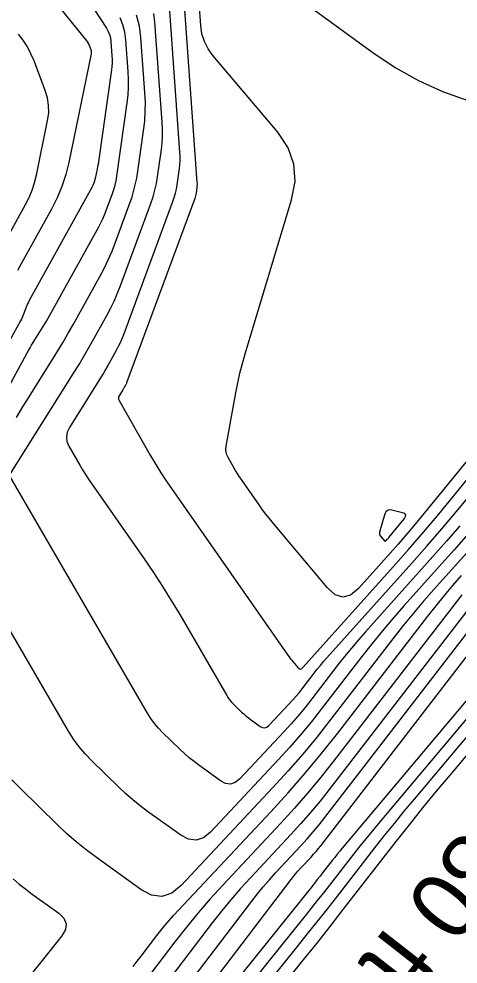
# Model space of a CAD drawing. Extents: x 7585033 to 7595090, y 547091 to 553471.
# Drawn here: x 7587336.2 to 7587377.6, y 548541.5 to 548630.8 of the extents above; entities that cross this region are included whole.
import ezdxf

# ---------------------------------------------------------------- set-up
doc = ezdxf.new("R2010")
doc.units = 0
for name, color, linetype in [('E_TERR_DSPLAY_GeneralTx', 7, 'Continuous'), ('E_TERR_DSPLAY_MajContour', 7, 'Continuous'), ('E_TERR_DSPLAY_MinContour', 7, 'Continuous')]:
    doc.layers.add(name, color=color, linetype=linetype)

msp = doc.modelspace()

# ---------------------------------------------------------------- linework, layer by layer
at = {"layer": 'E_TERR_DSPLAY_MajContour'}
for points in [[(7587351.655, 548633.394), (7587352.968, 548615.372), (7587352.974, 548615.242), (7587352.973, 548615.112), (7587352.965, 548614.982), (7587352.951, 548614.852), (7587352.877, 548614.335), (7587352.856, 548614.206), (7587352.827, 548614.079), (7587352.792, 548613.954), (7587352.751, 548613.831), (7587346.327, 548596.409), (7587346.305, 548596.353), (7587346.281, 548596.297), (7587346.254, 548596.242), (7587346.226, 548596.189), (7587346.108, 548595.976), (7587346.078, 548595.923), (7587346.047, 548595.87), (7587346.016, 548595.818), (7587345.984, 548595.767), (7587345.628, 548595.2), (7587345.574, 548595.088), (7587345.555, 548594.976), (7587345.57, 548594.862), (7587345.618, 548594.748), (7587348.563, 548589.606), (7587349.086, 548588.717), (7587349.628, 548587.841), (7587350.19, 548586.977), (7587350.771, 548586.125), (7587361.553, 548570.702), (7587361.66, 548570.552), (7587361.771, 548570.403), (7587361.885, 548570.258), (7587362.002, 548570.115), (7587362.477, 548569.547), (7587362.597, 548569.44), (7587362.717, 548569.403), (7587362.839, 548569.436), (7587362.962, 548569.538), (7587371.485, 548579.051), (7587372.937, 548580.69), (7587374.371, 548582.346), (7587375.785, 548584.018), (7587377.181, 548585.706), (7587394.741, 548607.188)], [(7587333.622, 548593.14), (7587336.924, 548599.198), (7587337.068, 548599.456), (7587337.215, 548599.712), (7587337.367, 548599.966), (7587337.522, 548600.218), (7587338.152, 548601.219), (7587338.308, 548601.47), (7587338.46, 548601.724), (7587338.609, 548601.979), (7587338.754, 548602.237), (7587343.702, 548611.15), (7587343.901, 548611.524), (7587344.084, 548611.905), (7587344.253, 548612.293), (7587344.407, 548612.688), (7587344.994, 548614.28), (7587345.13, 548614.681), (7587345.244, 548615.087), (7587345.336, 548615.499), (7587345.407, 548615.916), (7587346.385, 548622.851), (7587346.47, 548623.589), (7587346.514, 548624.328), (7587346.52, 548625.068), (7587346.485, 548625.81), (7587346.269, 548628.779), (7587346.171, 548629.507), (7587345.984, 548630.204), (7587345.71, 548630.872)], [(7587393.082, 548582.153), (7587370.08, 548554.8), (7587369.487, 548554.089), (7587368.901, 548553.372), (7587368.322, 548552.65), (7587367.749, 548551.923), (7587365.471, 548549.002), (7587364.9, 548548.273), (7587364.327, 548547.546), (7587363.751, 548546.821), (7587363.172, 548546.098), (7587339.031, 548516.049)], [(7587379.255, 548581.292), (7587375.325, 548576.906), (7587374.353, 548575.801), (7587373.402, 548574.678), (7587372.472, 548573.538), (7587371.562, 548572.381), (7587365.612, 548564.661), (7587364.301, 548563.002), (7587362.952, 548561.376), (7587361.564, 548559.783), (7587360.138, 548558.222), (7587351.47, 548548.96), (7587350.584, 548548.243), (7587349.657, 548547.943), (7587348.691, 548548.059), (7587347.683, 548548.591), (7587343.473, 548551.624), (7587342.509, 548552.345), (7587341.574, 548553.101), (7587340.667, 548553.891), (7587339.79, 548554.715), (7587336.335, 548558.08), (7587335.504, 548558.946)], [(7587340.403, 548524.208), (7587358.136, 548547.494), (7587358.675, 548548.182), (7587359.23, 548548.857), (7587359.803, 548549.517), (7587360.392, 548550.163), (7587362.783, 548552.718), (7587363.373, 548553.363), (7587363.947, 548554.022), (7587364.505, 548554.695), (7587365.047, 548555.381), (7587384.36, 548580.435)]]:
    msp.add_lwpolyline(points, dxfattribs=at)
at = {"layer": 'E_TERR_DSPLAY_MinContour'}
for points in [[(7587337.91, 548639.873), (7587344.429, 548629.889), (7587344.594, 548629.599), (7587344.719, 548629.296), (7587344.803, 548628.98), (7587344.848, 548628.649), (7587344.946, 548627.302), (7587344.962, 548626.966), (7587344.959, 548626.63), (7587344.939, 548626.294), (7587344.901, 548625.96), (7587343.708, 548617.511), (7587343.674, 548617.284), (7587343.637, 548617.056), (7587343.596, 548616.83), (7587343.551, 548616.604), (7587343.366, 548615.701), (7587343.312, 548615.479), (7587343.241, 548615.262), (7587343.154, 548615.051), (7587343.05, 548614.847), (7587337.139, 548604.185), (7587337.057, 548604.031), (7587336.982, 548603.875), (7587336.913, 548603.716), (7587336.85, 548603.554), (7587336.609, 548602.9), (7587336.546, 548602.738), (7587336.477, 548602.579), (7587336.402, 548602.423), (7587336.321, 548602.269), (7587334.589, 548599.136)], [(7587335.582, 548637.341), (7587342.576, 548628.658), (7587342.64, 548628.572), (7587342.696, 548628.482), (7587342.746, 548628.388), (7587342.787, 548628.29), (7587342.94, 548627.888), (7587342.971, 548627.786), (7587342.987, 548627.684), (7587342.987, 548627.581), (7587342.973, 548627.476), (7587340.872, 548617.23), (7587340.591, 548616.082), (7587340.226, 548614.965), (7587339.776, 548613.879), (7587339.242, 548612.824), (7587336.256, 548607.437), (7587336.029, 548607.009)], [(7587395.574, 548609.999), (7587374.125, 548583.758), (7587373.411, 548582.893), (7587372.686, 548582.037), (7587371.952, 548581.19), (7587371.209, 548580.35), (7587368.215, 548577.009), (7587367.47, 548576.386), (7587366.733, 548576.186), (7587366.002, 548576.411), (7587365.279, 548577.059), (7587360.18, 548583.156), (7587359.81, 548583.608), (7587359.45, 548584.068), (7587359.101, 548584.535), (7587358.761, 548585.01), (7587357.08, 548587.415), (7587356.919, 548587.65), (7587356.764, 548587.89), (7587356.613, 548588.132), (7587356.469, 548588.378), (7587355.901, 548589.369), (7587355.783, 548589.621), (7587355.714, 548589.882), (7587355.692, 548590.15), (7587355.719, 548590.427), (7587356.63, 548595.474), (7587356.812, 548596.405), (7587357.02, 548597.331), (7587357.255, 548598.25), (7587357.516, 548599.162), (7587361.903, 548613.706), (7587362.221, 548615.431), (7587362.108, 548617.067), (7587361.563, 548618.613), (7587360.587, 548620.071), (7587354.476, 548627.318), (7587354.015, 548627.957), (7587353.669, 548628.642), (7587353.438, 548629.374), (7587353.322, 548630.153), (7587352.98, 548634.852)], [(7587361.031, 548633.847), (7587369.572, 548627.599), (7587371.668, 548626.192), (7587373.859, 548624.971), (7587376.143, 548623.935), (7587378.52, 548623.085)], [(7587350.331, 548631.937), (7587351.332, 548618.192), (7587351.35, 548617.804), (7587351.347, 548617.416), (7587351.324, 548617.029), (7587351.28, 548616.642), (7587351.062, 548615.098), (7587350.997, 548614.715), (7587350.913, 548614.336), (7587350.808, 548613.963), (7587350.683, 548613.594), (7587346.025, 548600.962), (7587345.877, 548600.581), (7587345.714, 548600.207), (7587345.536, 548599.84), (7587345.345, 548599.479), (7587344.551, 548598.048), (7587344.35, 548597.691), (7587344.144, 548597.338), (7587343.933, 548596.987), (7587343.718, 548596.639), (7587340.925, 548592.2), (7587340.716, 548591.762), (7587340.641, 548591.322), (7587340.698, 548590.879), (7587340.888, 548590.433), (7587341.913, 548588.644), (7587342.174, 548588.199), (7587342.445, 548587.761), (7587342.725, 548587.33), (7587343.016, 548586.904), (7587347.985, 548579.796), (7587348.865, 548578.509), (7587349.717, 548577.205), (7587350.542, 548575.883), (7587351.339, 548574.544), (7587355.774, 548566.916), (7587355.915, 548566.691), (7587356.07, 548566.478), (7587356.239, 548566.275), (7587356.423, 548566.084), (7587357.185, 548565.341), (7587357.379, 548565.159), (7587357.579, 548564.985), (7587357.786, 548564.818), (7587357.999, 548564.658), (7587358.928, 548563.989), (7587359.151, 548563.871), (7587359.364, 548563.846), (7587359.569, 548563.912), (7587359.764, 548564.07), (7587361.678, 548566.115), (7587361.993, 548566.46), (7587362.3, 548566.812), (7587362.598, 548567.171), (7587362.887, 548567.537), (7587364.028, 548569.017), (7587364.316, 548569.384), (7587364.611, 548569.746), (7587364.913, 548570.102), (7587365.221, 548570.452), (7587373.233, 548579.394), (7587374.663, 548581.008), (7587376.074, 548582.638), (7587377.467, 548584.284), (7587378.841, 548585.946)], [(7587335.272, 548587.69), (7587341.451, 548597.512), (7587341.85, 548598.156), (7587342.24, 548598.805), (7587342.621, 548599.46), (7587342.993, 548600.119), (7587344.464, 548602.769), (7587344.819, 548603.437), (7587345.147, 548604.117), (7587345.448, 548604.81), (7587345.724, 548605.515), (7587348.615, 548613.358), (7587348.823, 548613.971), (7587348.998, 548614.593), (7587349.138, 548615.223), (7587349.246, 548615.861), (7587349.609, 548618.433), (7587349.682, 548619.076), (7587349.721, 548619.72), (7587349.726, 548620.366), (7587349.696, 548621.013), (7587349.007, 548630.479), (7587348.896, 548631.296)], [(7587335.944, 548593.152), (7587336.256, 548593.693), (7587336.576, 548594.229), (7587336.904, 548594.76), (7587339.332, 548598.619), (7587339.842, 548599.441), (7587340.34, 548600.271), (7587340.827, 548601.107), (7587341.302, 548601.95), (7587343.773, 548606.4), (7587344.199, 548607.204), (7587344.593, 548608.021), (7587344.956, 548608.854), (7587345.287, 548609.701), (7587346.548, 548613.121), (7587346.839, 548613.98), (7587347.083, 548614.849), (7587347.28, 548615.731), (7587347.43, 548616.625), (7587347.938, 548620.223), (7587348.041, 548621.123), (7587348.095, 548622.025), (7587348.102, 548622.928), (7587348.06, 548623.833), (7587347.682, 548629.021), (7587347.538, 548630.091), (7587347.264, 548631.117)], [(7587335.33, 548610.612), (7587336.787, 548613.241), (7587337.125, 548613.908), (7587337.409, 548614.594), (7587337.64, 548615.301), (7587337.818, 548616.027), (7587338.875, 548621.184), (7587338.973, 548621.907), (7587338.967, 548622.622), (7587338.859, 548623.329), (7587338.647, 548624.027), (7587337.592, 548626.803), (7587337.304, 548627.482), (7587336.964, 548628.133), (7587336.574, 548628.754), (7587336.134, 548629.347)], [(7587377.781, 548582.928), (7587376.519, 548581.47), (7587375.24, 548580.027), (7587368.875, 548572.923), (7587368.204, 548572.16), (7587367.547, 548571.385), (7587366.905, 548570.598), (7587366.277, 548569.799), (7587363.795, 548566.579), (7587363.165, 548565.781), (7587362.517, 548565), (7587361.85, 548564.234), (7587361.165, 548563.484), (7587356.999, 548559.033), (7587356.574, 548558.689), (7587356.129, 548558.545), (7587355.664, 548558.6), (7587355.18, 548558.856), (7587353.157, 548560.314), (7587352.694, 548560.66), (7587352.244, 548561.024), (7587351.809, 548561.403), (7587351.387, 548561.799), (7587349.727, 548563.416), (7587349.327, 548563.832), (7587348.959, 548564.273), (7587348.621, 548564.737), (7587348.315, 548565.226), (7587335.266, 548587.671)], [(7587392.726, 548583.466), (7587366.678, 548552.491), (7587366.438, 548552.204), (7587366.202, 548551.915), (7587365.968, 548551.624), (7587365.737, 548551.33), (7587364.818, 548550.152), (7587364.588, 548549.858), (7587364.357, 548549.565), (7587364.124, 548549.272), (7587363.891, 548548.98), (7587337.115, 548515.652)], [(7587378.375, 548581.932), (7587377.248, 548580.659), (7587372.529, 548575.393), (7587371.495, 548574.218), (7587370.484, 548573.024), (7587369.495, 548571.811), (7587368.527, 548570.581), (7587364.704, 548565.62), (7587363.733, 548564.392), (7587362.735, 548563.188), (7587361.707, 548562.009), (7587360.652, 548560.853), (7587354.234, 548553.997), (7587353.579, 548553.466), (7587352.893, 548553.244), (7587352.177, 548553.33), (7587351.431, 548553.724), (7587348.315, 548555.969), (7587347.601, 548556.503), (7587346.909, 548557.062), (7587346.238, 548557.647), (7587345.588, 548558.257), (7587343.031, 548560.748), (7587342.416, 548561.389), (7587341.848, 548562.068), (7587341.328, 548562.783), (7587340.856, 548563.536), (7587332.397, 548578.086)], [(7587337.417, 548517.449), (7587361.859, 548549.544), (7587362.077, 548549.822), (7587362.301, 548550.094), (7587362.532, 548550.36), (7587362.769, 548550.621), (7587363.734, 548551.651), (7587363.972, 548551.912), (7587364.203, 548552.177), (7587364.429, 548552.449), (7587364.647, 548552.726), (7587387.559, 548582.448)], [(7587340.947, 548516.445), (7587362.454, 548543.215), (7587363.377, 548544.369), (7587364.297, 548545.526), (7587365.213, 548546.687), (7587366.124, 548547.851), (7587369.761, 548552.515), (7587370.675, 548553.676), (7587371.6, 548554.829), (7587372.536, 548555.974), (7587373.482, 548557.109), (7587393.438, 548580.839)], [(7587361.735, 548540.332), (7587363.004, 548541.917), (7587364.267, 548543.507), (7587365.525, 548545.102), (7587366.777, 548546.701), (7587371.772, 548553.107), (7587373.028, 548554.703), (7587374.299, 548556.286), (7587375.584, 548557.858), (7587376.884, 548559.419), (7587393.794, 548579.526)], [(7587381.16, 548578.421), (7587365.447, 548558.037), (7587364.581, 548556.941), (7587363.691, 548555.867), (7587362.774, 548554.815), (7587361.833, 548553.785), (7587358.015, 548549.705), (7587357.074, 548548.674), (7587356.16, 548547.62), (7587355.273, 548546.543), (7587354.413, 548545.443), (7587343.388, 548530.967)], [(7587346.946, 548541.325), (7587347.321, 548541.811), (7587347.694, 548542.298), (7587349.181, 548544.25), (7587349.559, 548544.733), (7587349.949, 548545.206), (7587350.35, 548545.67), (7587350.763, 548546.123), (7587359.931, 548555.918), (7587361.577, 548557.719), (7587363.178, 548559.557), (7587364.734, 548561.434), (7587366.247, 548563.348), (7587374.762, 548574.394), (7587375.53, 548575.372), (7587376.316, 548576.336), (7587377.12, 548577.284), (7587377.941, 548578.218)], [(7587377.961, 548576.408), (7587365.847, 548560.692), (7587364.658, 548559.188), (7587363.434, 548557.712), (7587362.175, 548556.267), (7587360.882, 548554.851), (7587355.408, 548549.003), (7587354.229, 548547.71), (7587353.083, 548546.389), (7587351.971, 548545.039), (7587350.893, 548543.66), (7587346.374, 548537.726)], [(7587335.623, 548549.604), (7587336.203, 548549.098), (7587336.803, 548548.614), (7587337.42, 548548.151), (7587339.927, 548546.345), (7587340.416, 548545.874), (7587340.627, 548545.365), (7587340.563, 548544.817), (7587340.221, 548544.231), (7587336.26, 548539.231)]]:
    msp.add_lwpolyline(points, dxfattribs=at)
msp.add_lwpolyline([(7587370.184, 548582.223), (7587370.191, 548582.122), (7587370.225, 548582.027), (7587370.285, 548581.937), (7587370.654, 548581.495), (7587370.688, 548581.465), (7587370.722, 548581.454), (7587370.757, 548581.464), (7587370.792, 548581.493), (7587370.932, 548581.65), (7587370.967, 548581.689), (7587371.002, 548581.729), (7587371.036, 548581.769), (7587371.069, 548581.81), (7587372.55, 548583.621), (7587372.663, 548583.805), (7587372.671, 548583.956), (7587372.575, 548584.072), (7587372.374, 548584.153), (7587371.363, 548584.41), (7587371.133, 548584.435), (7587370.947, 548584.382), (7587370.806, 548584.249), (7587370.71, 548584.039), (7587370.203, 548582.329)], close=True, dxfattribs=at)

# ---------------------------------------------------------------- texts
at = {"layer": 'E_TERR_DSPLAY_GeneralTx'}
msp.add_text('180 ft', height=6.3, rotation=231.97605, dxfattribs=at).set_placement((7587381.063, 548558.224))

doc.saveas('drawing.dxf')
